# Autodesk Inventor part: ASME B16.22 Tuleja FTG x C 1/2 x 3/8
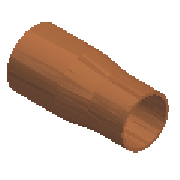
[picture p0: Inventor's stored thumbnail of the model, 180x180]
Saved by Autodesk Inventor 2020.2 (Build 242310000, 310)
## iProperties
Manager: www.cadconsulting.pl
Company: Fabian Stasiak CAD Consulting
IsCustomPart: 0
NAME: PIPING: ASME B16.22 Bushing FTG x C
DATA: <meta><inlinegroups number="1" deflen="2.54"></inlinegroups><connections number="2"></connections><angles><a>3.14159265358979</a></angles></meta>
Created: 2014-02
Part Number: ASME B16.22 Tuleja FTG x C 1/2 x 3/8
Material: Miedź kuta
Description: Tuleja
Document SubType Name: Modeling
Standard: ASME B16.22
Designer: F.Stasiak
Standard Revision: 2001
Standards Organization: ANSI
Language: pl-PL
Size Designation: 1/2 x 3/8
Categories: <MemberInstance><Categories><Category DisplayName="Rury cienko- i grubościenne" InternalName="4347fa0f-2144-441d-94cd-e3e15c92b736" Mnemonic="TUBEANDPIPE"><Cate
Density: 1 g/cm^3
Appearance: Miedź - satynowa
Catalog Web Link: www.expertbooks.pl
Author: F.Stasiak
Subject: Zbiór ćwiczeń. Autodesk Inventor 2020. Kurs Professional
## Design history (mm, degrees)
sketch "Sketch1"
  geometry: L1 (0, 0)-(-33.528, 0); L2 (0, 0)-(0, 7.163); L3 (0, 7.163)-(0, 7.899); L4 (0, 7.899)-(-14.224, 7.899); L5 (-14.224, 7.899)-(-23.876, 7.036); L6 (-23.876, 7.036)-(-33.528, 7.036); L7 (-33.528, 7.036)-(-33.528, 6.375); L8 (-33.528, 6.375)-(-23.883, 6.375); L9 (-14.224, 7.163)-(0, 7.163); L10 (-33.528, 6.375)-(-33.528, 0); L11 (-23.876, 7.036)-(-23.876, 0); L12 (-14.224, 7.899)-(-14.224, 7.163); L13 (-23.876, 6.299)-(-14.224, 7.163); L14 (-23.876, 6.299)-(-23.883, 6.375); L15 (-14.224, 7.163)-(-14.224, 0); 1 further point
  constraints: 30 end point, 6 perpendicular, 5 parallel, 3 point on line, 1 coincident, 1 collinear, 1 horizontal
  dimensions: "d0" = 0.6604 distance of L6.end L7.end (= T2); "d1" = 0.7366 distance of L2.end L3.end (= T1); "d2" = 7.8994 distance of L1.start L3.end (= 0.5 x A); "d3" = 6.3754 distance of L7.end L1.end (= 0.5 x F1); "d4" = 9.652 distance of L11.end L1.end (= G); "d5" = 14.224 horizontal distance of L9.start L1.start (= K1); "d6" = 23.876 distance of L1.start L11.end (= L); "d7" = 0.7366 distance of L13.start L5.end (= T1)
revolve "Revolve1" sketch "Sketch1" stored, may be unused: angle "d9" = 90 deg
workpoint "Work Point1"
workpoint "Work Point2"
workaxis "Work Axis1"
workpoint "Work Point3"
workaxis "Work Axis2"
workpoint "Work Point4"
body "Solid1"
other parameters: "L" = 23.876 [user parameter; used in 1 equation term], "G" = 9.652 [user parameter; used in 1 equation term], "T1" = 0.7366 [user parameter; used in 2 equation terms], "F1" = 12.7508 [user parameter; used in 1 equation term], "A" = 15.7988 [user parameter; used in 1 equation term], "T2" = 0.6604 [user parameter; used in 1 equation term], "K1" = 14.224 [user parameter; used in 1 equation term], "Size_Designation" = 12.345 [user parameter]
